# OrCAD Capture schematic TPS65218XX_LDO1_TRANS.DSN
size E; title: TPS65218D0 Power Management for ARM® Cortex™-A8/A9; rev: 1.0; note: Datasheet:SLDS234B     EVM:NA; note: Synchronous Step Down Converter
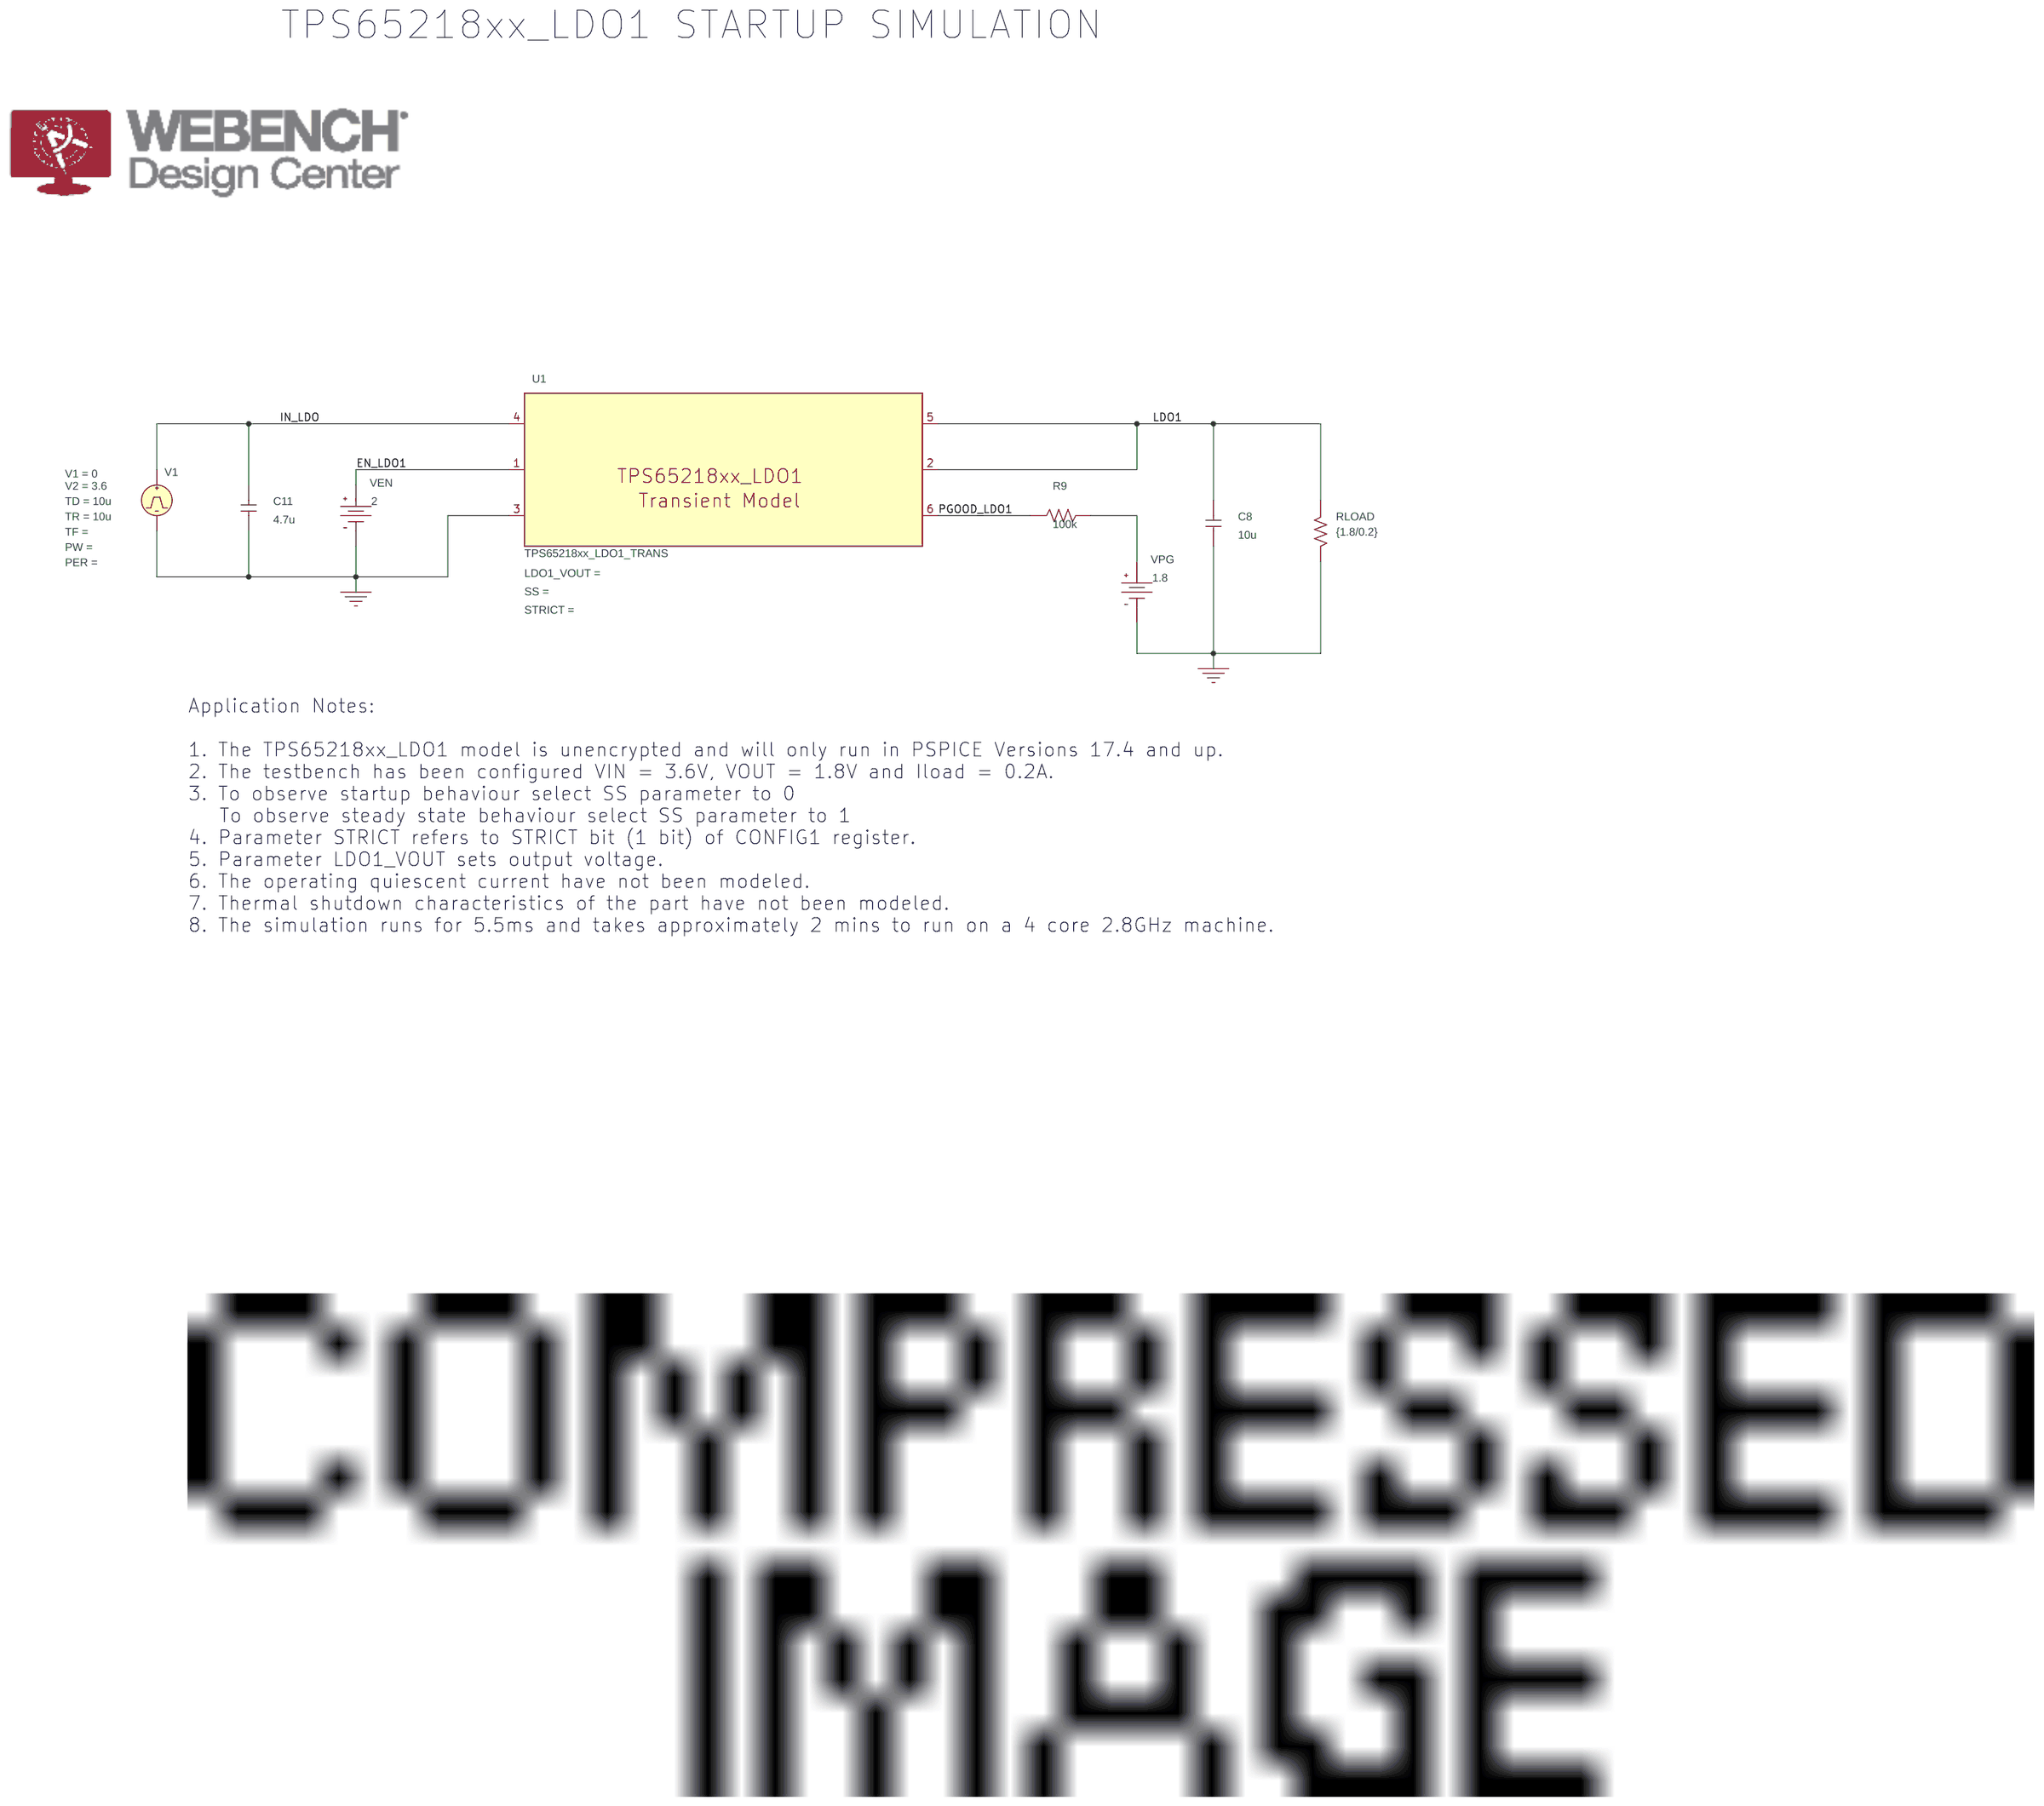
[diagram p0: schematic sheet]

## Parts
C8  10u  [RAD/CK05]
C11  4.7u  [RAD/CK05]
R9  100k  [AX/RC05]
RLOAD  {1.8/0.2}  [AX/RC05]
U1  TPS65218xx_LDO1_TRANS
V1  VPULSE
VEN  VDC
VPG  VDC

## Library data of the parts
C8 C11 = C
R9 RLOAD = R
U1 = TPS65218XX_LDO1_TRANS
V1 = VPULSE: TD: 10u; TR: 10u; V1: 0; V2: 3.6
VEN = VDC: DC: 2
VPG = VDC: DC: 1.8

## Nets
0: C8.2 C11.2 RLOAD.2 U1.3(GND) V1.2(-) VEN.1(-) VPG.1(-)
EN_LDO1: U1.1(EN_LDO1) VEN.0(+)
IN_LDO: C11.1 U1.4(IN_LDO1) V1.1(+)
LDO1: C8.1 RLOAD.1 U1.2(FB_LDO1) U1.5(LDO1)
PGOOD_LDO1: R9.1 U1.6(PGOOD_LDO1)
N16777346: R9.2 VPG.0(+)

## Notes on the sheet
- TPS65218xx_LDO1 STARTUP SIMULATION
- Application Notes:
  1. The TPS65218xx_LDO1 model is unencrypted and will only run in PSPICE Versions 17.4 and up.
  2. The testbench has been configured VIN = 3.6V, VOUT = 1.8V and Iload = 0.2A.
  3. To observe startup behaviour select SS parameter to 0
     To observe steady state behaviour select SS parameter to 1
  4. Parameter STRICT refers to STRICT bit (1 bit) of CONFIG1 register.
  5. Parameter LDO1_VOUT sets output voltage.
  6. The operating quiescent current have not been modeled.
  7. Thermal shutdown characteristics of the part have not been modeled.
  8. The simulation runs for 5.5ms and takes approximately 2 mins to run on a 4 core 2.8GHz machine.
